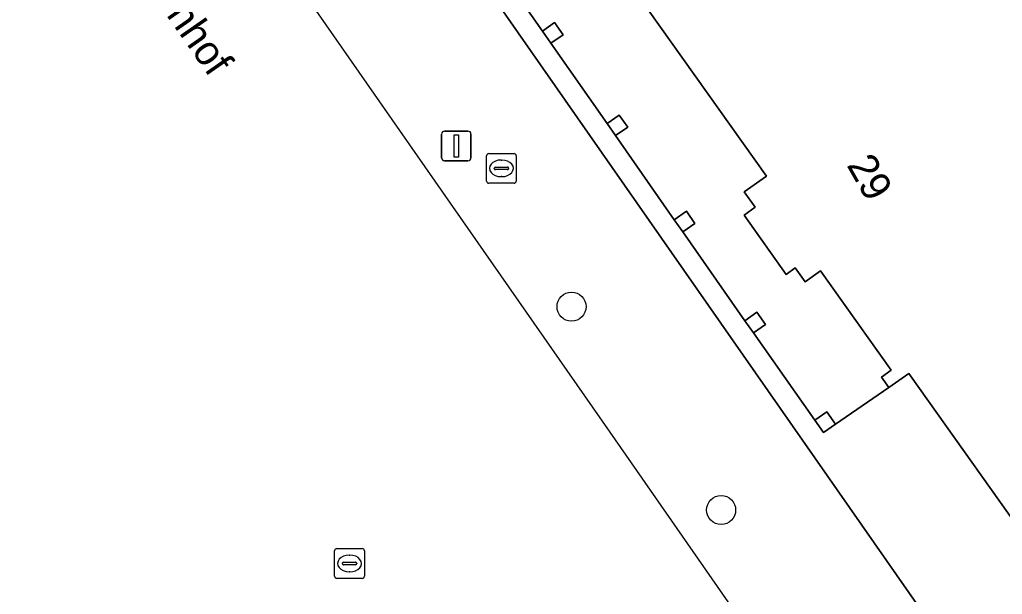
# Model space of a CAD drawing. Extents: x 161087 to 161926, y 382572 to 383873.
# Drawn here: x 161452.07 to 161485.18, y 383012.71 to 383032.06 of the extents above; entities that cross this region are included whole.
import ezdxf

# ---------------------------------------------------------------- set-up
doc = ezdxf.new("R2010")
doc.units = 0
for name, color, linetype in [('IMGEO_Boom', 7, 'Continuous'), ('IMGEO_Erf', 7, 'Continuous'), ('IMGEO_Kolk', 7, 'Continuous'), ('IMGEO_Lichtmast', 7, 'Continuous'), ('IMGEO_Lijnafwatering', 7, 'Continuous'), ('IMGEO_Openbare_ruimte_label', 7, 'Continuous'), ('IMGEO_Pand', 7, 'Continuous'), ('IMGEO_Pand_nummerreeks', 7, 'Continuous'), ('IMGEO_Rioolput', 7, 'Continuous'), ('IMGEO_Voetgangersgebied_open', 7, 'Continuous')]:
    doc.layers.add(name, color=color, linetype=linetype)

msp = doc.modelspace()

# ---------------------------------------------------------------- linework, layer by layer
at = {"layer": 'IMGEO_Boom'}
for centre in [(161470.664, 383022.393), (161475.704, 383015.546)]:
    msp.add_circle(centre, 0.489, dxfattribs=at)
at = {"layer": 'IMGEO_Erf'}
msp.add_lwpolyline([(161467.681, 383034.544), (161469.685, 383031.674), (161470.094, 383031.96), (161470.38, 383031.55), (161469.972, 383031.265), (161471.862, 383028.56), (161472.271, 383028.846), (161472.557, 383028.436), (161472.149, 383028.151), (161474.125, 383025.322), (161474.534, 383025.608), (161474.82, 383025.198), (161474.412, 383024.913), (161476.502, 383021.92), (161476.911, 383022.206), (161477.197, 383021.796), (161476.789, 383021.511), (161478.86, 383018.566), (161479.269, 383018.852), (161479.555, 383018.442), (161481.358, 383019.668), (161481.105, 383020.024), (161481.428, 383020.254), (161479.054, 383023.596), (161478.534, 383023.227), (161478.2, 383023.696), (161477.896, 383023.48), (161476.48, 383025.473), (161476.854, 383025.738), (161476.485, 383026.257), (161477.229, 383026.785), (161469.619, 383037.497)], dxfattribs=at)
at = {"layer": 'IMGEO_Kolk'}
for p, q in [((161467.803, 383026.624), (161467.803, 383027.476)), ((161467.878, 383027.55), (161468.73, 383027.55)), ((161468.291, 383027.33), (161468.316, 383027.33)), ((161468.804, 383027.476), (161468.804, 383026.624)), ((161468.062, 383027.044), (161468.062, 383027.056)), ((161468.5, 383027.007), (161468.102, 383027.007)), ((161468.105, 383027.093), (161468.503, 383027.093)), ((161468.546, 383027.056), (161468.546, 383027.044)), ((161468.314, 383026.77), (161468.289, 383026.77)), ((161468.73, 383026.55), (161467.878, 383026.55))]:
    msp.add_line(p, q, dxfattribs=at)
for points in [[(161467.803, 383026.624), (161467.803, 383027.476)], [(161467.878, 383027.55), (161468.73, 383027.55)], [(161468.804, 383027.476), (161468.804, 383026.624)], [(161468.73, 383026.55), (161467.878, 383026.55)]]:
    msp.add_lwpolyline(points, dxfattribs=at)
for centre, radius, start, end in [((161467.88, 383027.474), 0.0765, 91.552, 178.448), ((161467.88, 383027.474), 0.0765, 91.552, 178.448), ((161468.728, 383027.474), 0.0765, 1.552, 88.448), ((161468.728, 383027.474), 0.0765, 1.552, 88.448), ((161468.102, 383027.053), 0.0403, 85.8775, 175.7526), ((161468.099, 383027.043), 0.0366, 178.938, 274.7102), ((161468.503, 383027.05), 0.043, 264.8664, 352.4533), ((161468.507, 383027.055), 0.0386, 1.7309, 96.639), ((161467.88, 383026.626), 0.0765, 181.552, 268.448), ((161467.88, 383026.626), 0.0765, 181.552, 268.448), ((161468.728, 383026.626), 0.0765, 271.552, 358.448), ((161468.728, 383026.626), 0.0765, 271.552, 358.448)]:
    msp.add_arc(centre, radius, start, end, dxfattribs=at)
for centre, major_axis, ratio, start_param, end_param in [((161468.29, 383027.05), (-0.387, 0.002), 0.722429, 4.712389, 7.853982), ((161468.315, 383027.05), (-0.39, 0.002), 0.717154, 1.570796, 4.712389)]:
    msp.add_ellipse(centre, major_axis=major_axis, ratio=ratio, start_param=start_param, end_param=end_param, dxfattribs=at)
at = {"layer": 'IMGEO_Lichtmast'}
for p, q in [((161466.386, 383028.304), (161467.176, 383028.304)), ((161467.176, 383028.304), (161466.386, 383028.304)), ((161466.286, 383027.404), (161466.286, 383028.204)), ((161466.286, 383028.204), (161466.286, 383027.404)), ((161467.276, 383028.204), (161467.276, 383027.404)), ((161467.276, 383027.404), (161467.276, 383028.204)), ((161467.176, 383027.304), (161466.386, 383027.304)), ((161466.386, 383027.304), (161467.176, 383027.304))]:
    msp.add_line(p, q, dxfattribs=at)
msp.add_lwpolyline([(161466.706, 383028.179), (161466.856, 383028.179), (161466.856, 383027.429), (161466.706, 383027.429), (161466.706, 383028.179)], dxfattribs=at)
for centre, start, end in [((161466.386, 383028.204), 90, 180), ((161466.386, 383028.204), 90, 180), ((161467.176, 383028.204), 0, 90), ((161467.176, 383028.204), 360, 90), ((161466.386, 383027.404), 180, 270), ((161466.386, 383027.404), 180, 270), ((161467.176, 383027.404), 270, 0), ((161467.176, 383027.404), 270, 0)]:
    msp.add_arc(centre, 0.1, start, end, dxfattribs=at)
at = {"layer": 'IMGEO_Lijnafwatering'}
for points in [[(161471.96, 383018.162), (161458.989, 383036.791)], [(161484.606, 383000.001), (161471.96, 383018.162)]]:
    msp.add_lwpolyline(points, dxfattribs=at)
at = {"layer": 'IMGEO_Pand'}
msp.add_lwpolyline([(161469.619, 383037.497), (161477.229, 383026.785), (161476.485, 383026.257), (161476.854, 383025.738), (161476.48, 383025.473), (161477.896, 383023.48), (161478.2, 383023.696), (161478.534, 383023.227), (161479.054, 383023.596), (161481.428, 383020.254), (161481.105, 383020.024), (161481.358, 383019.668), (161482.027, 383020.143), (161485.721, 383014.943), (161485.837, 383015.025), (161489.111, 383017.351), (161489.521, 383016.774), (161497.04, 383022.116), (161496.02, 383023.552), (161498.21, 383025.108), (161498.755, 383024.34), (161499.891, 383025.147), (161496.378, 383030.091), (161500, 383033.453)], dxfattribs=at)
for points in [[(161470.094, 383031.96), (161469.685, 383031.674), (161469.972, 383031.265), (161470.38, 383031.55)], [(161472.271, 383028.846), (161471.862, 383028.56), (161472.149, 383028.151), (161472.557, 383028.436)], [(161474.534, 383025.608), (161474.125, 383025.322), (161474.412, 383024.913), (161474.82, 383025.198)], [(161476.911, 383022.206), (161476.502, 383021.92), (161476.789, 383021.511), (161477.197, 383021.796)], [(161479.269, 383018.852), (161478.86, 383018.566), (161479.147, 383018.157), (161479.555, 383018.442)]]:
    msp.add_lwpolyline(points, close=True, dxfattribs=at)
at = {"layer": 'IMGEO_Rioolput'}
for p, q in [((161462.684, 383013.32), (161462.684, 383014.172)), ((161462.759, 383014.246), (161463.611, 383014.246)), ((161463.172, 383014.026), (161463.197, 383014.026)), ((161463.685, 383014.172), (161463.685, 383013.32)), ((161462.943, 383013.74), (161462.943, 383013.752)), ((161463.381, 383013.703), (161462.983, 383013.703)), ((161462.986, 383013.789), (161463.384, 383013.789)), ((161463.427, 383013.752), (161463.427, 383013.74)), ((161463.195, 383013.466), (161463.17, 383013.466)), ((161463.611, 383013.246), (161462.759, 383013.246))]:
    msp.add_line(p, q, dxfattribs=at)
for points in [[(161462.684, 383013.32), (161462.684, 383014.172)], [(161462.759, 383014.246), (161463.611, 383014.246)], [(161463.685, 383014.172), (161463.685, 383013.32)], [(161463.611, 383013.246), (161462.759, 383013.246)]]:
    msp.add_lwpolyline(points, dxfattribs=at)
for centre, radius, start, end in [((161462.761, 383014.17), 0.0765, 91.552, 178.448), ((161462.761, 383014.17), 0.0765, 91.552, 178.448), ((161463.609, 383014.17), 0.0765, 1.552, 88.448), ((161463.609, 383014.17), 0.0765, 1.552, 88.448), ((161462.983, 383013.749), 0.0403, 85.8775, 175.7526), ((161462.98, 383013.739), 0.0366, 178.938, 274.7102), ((161463.384, 383013.746), 0.043, 264.8664, 352.4533), ((161463.388, 383013.751), 0.0386, 1.7309, 96.639), ((161462.761, 383013.322), 0.0765, 181.552, 268.448), ((161462.761, 383013.322), 0.0765, 181.552, 268.448), ((161463.609, 383013.322), 0.0765, 271.552, 358.448), ((161463.609, 383013.322), 0.0765, 271.552, 358.448)]:
    msp.add_arc(centre, radius, start, end, dxfattribs=at)
for centre, major_axis, ratio, start_param, end_param in [((161463.171, 383013.746), (-0.387, 0.002), 0.722429, 4.712389, 7.853982), ((161463.196, 383013.746), (-0.39, 0.002), 0.717154, 1.570796, 4.712389)]:
    msp.add_ellipse(centre, major_axis=major_axis, ratio=ratio, start_param=start_param, end_param=end_param, dxfattribs=at)
at = {"layer": 'IMGEO_Voetgangersgebied_open'}
msp.add_lwpolyline([(161436.953, 383077.304), (161432.896, 383074.264), (161410.333, 383057.358), (161412.451, 383054.33), (161427.003, 383033.515), (161429.943, 383029.064), (161430.511, 383028.577), (161432.084, 383029.67), (161452.689, 383000), (161453.475, 382998.869), (161463.693, 383005.964), (161466.917, 383001.359), (161482.447, 383012.169)], close=True, dxfattribs=at)
for points in [[(161436.953, 383077.304), (161482.447, 383012.169), (161483.461, 383010.717), (161490.993, 382999.933)], [(161485.721, 383014.943), (161482.027, 383020.143), (161481.358, 383019.668), (161479.555, 383018.442), (161479.147, 383018.157), (161478.86, 383018.566), (161476.789, 383021.511), (161476.502, 383021.92), (161474.412, 383024.913), (161474.125, 383025.322), (161472.149, 383028.151), (161471.862, 383028.56), (161469.972, 383031.265), (161469.685, 383031.674), (161467.681, 383034.544)]]:
    msp.add_lwpolyline(points, dxfattribs=at)

# ---------------------------------------------------------------- texts
at = {"layer": 'IMGEO_Openbare_ruimte_label'}
msp.add_text('Begijnenhof', height=1, rotation=304.8981, dxfattribs=at).set_placement((161454.444, 383035.877))
at = {"layer": 'IMGEO_Pand_nummerreeks'}
msp.add_text('29', height=1, rotation=299.7816, dxfattribs=at).set_placement((161479.918, 383027.16))

doc.saveas('drawing.dxf')
